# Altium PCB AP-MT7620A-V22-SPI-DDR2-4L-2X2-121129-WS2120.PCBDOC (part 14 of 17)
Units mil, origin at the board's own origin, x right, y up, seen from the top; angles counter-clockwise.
Board outline 7316 x 4279 mil, 4 copper layers (Top, Inner Layer 2, Inner Layer 3, Bottom), stack 35.4 mil thick; 640 components, 473 nets, 2041 pads, 2358 vias.
Unrouted connection lines stored in the file: 11.
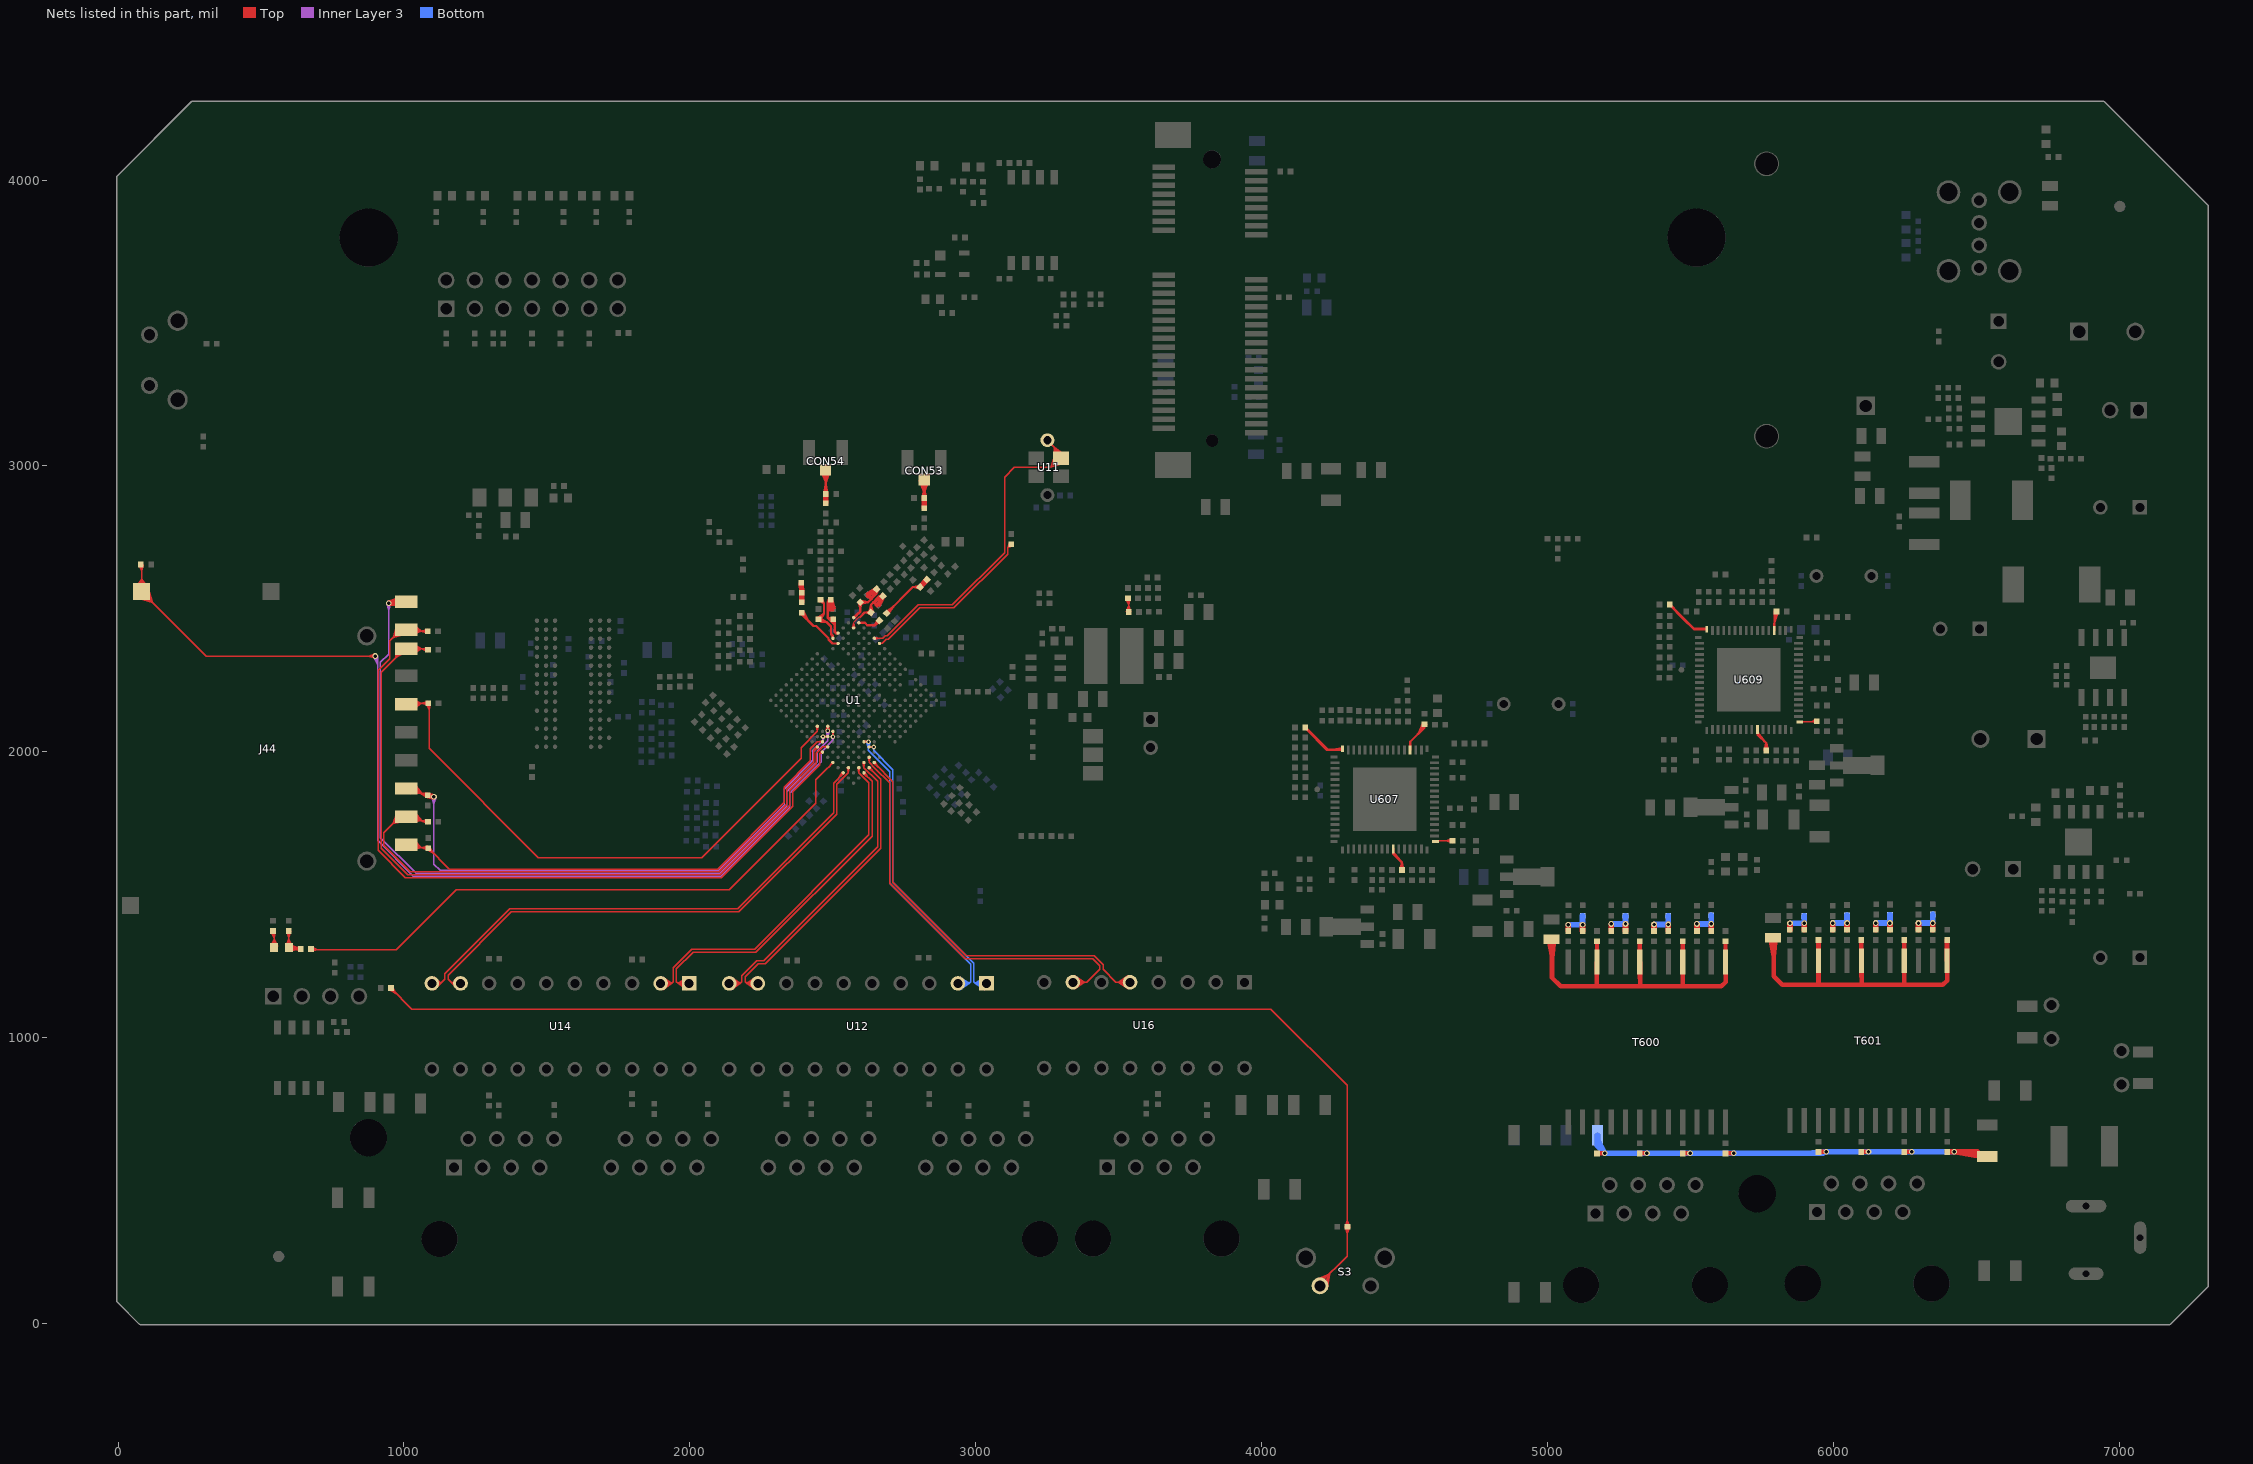
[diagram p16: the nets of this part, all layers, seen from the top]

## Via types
v1: diameter 20, hole 12, Top to Bottom, 2117 vias
v2: diameter 16, hole 8, Top to Bottom, 241 vias

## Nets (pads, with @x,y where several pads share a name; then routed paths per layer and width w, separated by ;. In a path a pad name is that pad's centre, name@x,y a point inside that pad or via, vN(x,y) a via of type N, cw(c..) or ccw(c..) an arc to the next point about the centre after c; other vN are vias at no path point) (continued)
PMCT_HV_GE_4-ETHERNET: C732.1 C735.1 R795.1 R796.1 R797.1 R798.1 R803.1 R804.1 R805.1 R806.1 | length 2327.8
  Top w15: R797.1@5473.05,595.01 R797.1@5474.04,596 ; R797.1@5473.05,595.01 v1(5499,596) ; R797.1@5473.05,595.01 v1(5499,596) ; R797.1@5474.04,596 v1(5499,596) ; R797.1@5474.04,596 v1(5499,596) ; R805.1@6248.05,600.01 R805.1@6249.04,601 ; R805.1@6248.05,600.01 v1(6274,601) ; R805.1@6248.05,600.01 v1(6274,601) ; R805.1@6249.04,601 v1(6274,601) ; R805.1@6249.04,601 v1(6274,601) ; R795.1@5173.05,595.01 5174.04,596 v1(5200,596) R795.1@5173.05,595.01 ; R796.1@5323.05,595.01 5324.04,596 v1(5348,596) R796.1@5323.05,595.01 ; R798.1@5623.05,595.01 5624.04,596 v1(5652,596) R798.1@5623.05,595.01 ; R803.1@5948.05,600.01 5949.04,601 v1(5975,601) R803.1@5948.05,600.01 ; R804.1@6098.05,600.01 6099.04,601 v1(6123,601) R804.1@6098.05,600.01
  Top w20: R806.1@6398.05,600.01 v1(6423,601) ; R806.1@6398.05,601.01 v1(6423,601) ; v1@6431.84,601 C732.1@6522.25,584.88 ; 6494.56,589.82 v1(6423,601) ; C732.1@6538,584.88 6538,588 6516,588 6503,601 v1(6423,601)
  Bottom w20: C735.1@5175.24,658.56 5175.06,658.38 5175.06,622 ; 5898.21,596.01 v1(5975,601) ; v1(6423,601) v1(6274,601) v1(6123,601) v1(5975,601) ; 5175.06,622 v1@5200,597.06 ; 5175.06,622 v1(5200,596) ; v1(5200,596) v1(5348,596) v1(5499,596) v1(5652,596) 5963.01,596.01 5968,601 v1(5975,601) ; v1(5200,596) v1@5200,597.06 ; v1(5200,596) 5175.24,642.81 v1@5200,597.06
POWERLED_6-LED1: D7.1 R158.1 | length 377.5
  Top w4.5: R158.1@534.68,1370.45 546.41,1348.56 ; D7.1@534.93,1320.51 546.41,1345.5 ; R158.1@538.85,1372.21 546.41,1348.56 ; D7.1@539.22,1318.96 546.41,1345.5 ; D7.1@543.66,1318.14 546.41,1345.5 ; R158.1@545.23,1373.37 546.41,1348.56 ; D7.1@546.41,1316 546.41,1369.59 542,1374 R158.1@542,1373 546.41,1348.56 ; D7.1@546.41,1318 546.41,1345.5 ; D7.1@549.16,1318.14 546.41,1345.5 ; R158.1@549.75,1373.17 546.41,1348.56 ; D7.1@553.6,1318.96 546.41,1345.5 ; D7.1@557.89,1320.51 546.41,1345.5
PRSET_IP1001-2_1-CPU-RT0: R744.1 U609.17 | length 154.1
  Top w5: U609.17@5882.16,2104.41 5895,2104.41 ; 5908.97,2105 U609.17@5889.05,2104.41 ; R744.1@5938.91,2113.89 5927,2104.41 ; R744.1@5941.43,2099.57 5927,2104.41 ; U609.17@5889.05,2104.41 5895.59,2105 ; U609.17@5889.05,2104.41 5895,2104.41 ; U609.17@5889.05,2104.41 5895,2104.41 ; U609.17@5889.05,2104.41 5895.59,2105 ; 5895,2104.41 5895.59,2105 ; 5895.59,2105 5926.41,2105 5927,2104.41 ; 5927,2104.41 5940.35,2104.41 5942.99,2107.05 R744.1@5941.99,2107.05 5927,2104.41
PRSET_IP1001_1-CPU-RT0: R723.1 U607.17 | length 159.8
  Top w5: U607.17@4608.16,1686.41 4608.16,1689.06 4668.98,1689.06 R723.1@4667.99,1689.05 4642.99,1689.06 ; U607.17@4615.05,1686.41 4635.16,1689.06 ; R723.1@4666.86,1681.64 4642.99,1689.06 ; R723.1@4666.87,1696.47 4642.99,1689.06
PTC1_GE_2_4-ETHERNET: C813.1 R801.1 R802.1 | length 275
  Top w20: R801.1@6298,1378.06 R801.1@6298.05,1378.01 v1(6298,1401) ; R801.1@6298,1378.06 v1(6298,1401) ; R801.1@6298,1378.06 v1(6298,1401) ; R802.1@6348.05,1378.01 v1(6348.05,1401) R802.1@6348.05,1378.01
  Bottom w20: v1(6348.05,1401) v1(6298,1401) v1(6348.05,1401) ; v1(6348.05,1401) C813.1@6348,1431 C813.1@6348,1431 v1(6348.05,1401)
PTC1_GE_4-ETHERNET: C809.1 R789.1 R790.1 | length 309.9
  Top w20: R789.1@5523,1373.06 R789.1@5523.05,1373.01 v1(5523,1398) ; R789.1@5523,1373.06 v1(5523,1398) ; R789.1@5523,1373.06 v1(5523,1398) ; R790.1@5573,1373.06 v1(5573,1398) ; R790.1@5573,1373.06 R790.1@5573.05,1373.01 v1(5573,1398) ; R790.1@5573,1373.06 v1(5573,1398)
  Bottom w20: v1(5573,1398) v1(5523,1398) v1(5573,1398) ; v1(5573,1398) C809.1@5573,1428 v1(5573,1398)
PTC2_GE_2_4-ETHERNET: C812.1 R799.1 R800.1 | length 295.9
  Top w20: R799.1@6148,1378.06 R799.1@6148.05,1378.01 v1(6148,1401) ; R799.1@6148,1378.06 v1(6148,1401) ; R799.1@6148,1378.06 v1(6148,1401) ; R800.1@6198,1378.06 v1(6198,1401) ; R800.1@6198,1378.06 R800.1@6198.05,1378.01 v1(6198,1401) ; R800.1@6198,1378.06 v1(6198,1401)
  Bottom w20: v1(6198,1401) v1(6148,1401) v1(6198,1401) ; v1(6198,1401) C812.1@6198,1430 v1(6198,1401)
PTC2_GE_4-ETHERNET: C808.1 R787.1 R788.1 | length 277
  Top w20: R788.1@5423,1373.06 v1(5423,1396) ; R788.1@5423,1373.06 R788.1@5423.05,1373.01 v1(5423,1396) ; R788.1@5423,1373.06 v1(5423,1396) ; R787.1@5373,1373.06 R787.1@5373.05,1373.01 v1(5373,1396) R787.1@5373,1373.06
  Bottom w20: v1(5423,1396) v1(5373,1396) v1(5423,1396) ; v1(5423,1396) C808.1@5423.05,1427 C808.1@5423.05,1427 v1(5423,1396)
PTC3_GE_2_4-ETHERNET: C815.1 R793.1 R794.1 | length 268.9
  Top w20: R793.1@5998,1378.06 R793.1@5998.05,1378.01 v1(5998,1401) ; R793.1@5998,1378.06 v1(5998,1401) ; R793.1@5998,1378.06 v1(5998,1401) ; v1(6048,1401) v1(6048,1401) R794.1@6048.05,1378.01 v1(6048,1401)
  Bottom w20: v1(6048,1401) v1(5998,1401) v1(6048,1401) ; v1(6048,1401) C815.1@6048,1428 v1(6048,1401)
PTC3_GE_4-ETHERNET: C807.1 R785.1 R786.1 | length 258
  Top w20: v1(5223,1398) v1(5223,1398) R785.1@5223.05,1373.01 v1(5223,1398) ; v1(5273,1398) v1(5273,1398) R786.1@5273.05,1373.01 v1(5273,1398)
  Bottom w20: v1(5273,1398) v1(5223,1398) v1(5273,1398) ; v1(5273,1398) C807.1@5273.05,1427 C807.1@5273.05,1427 v1(5273,1398)
PTC4_GE_2_4-ETHERNET: C811.1 R791.1 R792.1 | length 307.1
  Top w20: R791.1@5848.05,1378.01 R791.1@5848.5,1378.46 ; R791.1@5848.05,1378.01 v1(5848.5,1400.5) ; R791.1@5848.05,1378.01 v1(5848.5,1400.5) ; R791.1@5848.5,1378.46 v1(5848.5,1400.5) ; R791.1@5848.5,1378.46 v1(5848.5,1400.5) ; R792.1@5898,1378.06 R792.1@5898.05,1378.01 v1(5898,1400.5) ; R792.1@5898,1378.06 v1(5898,1400.5) ; R792.1@5898,1378.06 v1(5898,1400.5)
  Bottom w20: v1(5898,1400.5) v1(5848.5,1400.5) v1(5898,1400.5) ; v1(5898,1400.5) C811.1@5898,1426 v1(5898,1400.5)
PTC4_GE_4-ETHERNET: C806.1 R783.1 R784.1 | length 275.5
  Top w20: R784.1@5123,1373.06 v1(5123,1395.5) ; R784.1@5123,1373.06 R784.1@5123.05,1373.01 v1(5123,1395.5) ; R784.1@5123,1373.06 v1(5123,1395.5) ; v1(5073,1395.5) 5073.05,1395.45 R783.1@5073.05,1373.01 v1(5073,1395.5)
  Bottom w20: v1(5123,1395.5) v1(5073,1395.5) v1(5123,1395.5) ; v1(5123,1395.5) C806.1@5123.05,1427 C806.1@5123.05,1427 v1(5123,1395.5)
PTCT_GE_2_4-ETHERNET: C726.2 C727.2 C728.2 C730.2 L622.2 T601.1 T601.4 T601.7 T601.10 | length 1972.8
  Top w15: T601.7@6098.05,1269.54 C727.2@6098.05,1342.01 T601.7@6098.05,1303.79 ; T601.4@6248.05,1269.54 C728.2@6248.05,1342.01 T601.4@6248.05,1303.79
  Top w16: L622.2@5780.09,1348.66 5791.05,1284.46 ; L622.2@5798.04,1349.22 5791.05,1284.46 ; T601.10@5948.05,1235.29 5948.05,1185.01 ; T601.10@5948.05,1269.54 5948.05,1185.01 ; T601.7@6098.05,1235.29 6099.05,1185.01 ; T601.7@6098.05,1269.54 6099.05,1268.54 6099.05,1185.01 ; T601.4@6248.05,1235.29 6248.05,1185.01 ; T601.4@6248.05,1269.54 6248.05,1185.01 ; T601.1@6398.05,1235.29 6398.05,1200.01 ; T601.1@6398.05,1269.54 6398.05,1200.01 ; 5791.05,1284.46 L622.2@5789.05,1349.56 5791.05,1347.56 5791.05,1215.01 5821.05,1185.01 5948.05,1185.01 ; 5948.05,1185.01 6099.05,1185.01 ; 6099.05,1185.01 6248.05,1185.01 ; 6248.05,1185.01 6383.05,1185.01 6398.05,1200.01
  Top w18: T601.10@5948.05,1269.54 C726.2@5948.05,1342.01 T601.10@5948.05,1303.79 ; T601.1@6398,1278 C730.2@6398,1342 ; T601.1@6398.05,1269.54 6398,1269.59 C730.2@6398,1342 ; T601.1@6398.05,1303.79 C730.2@6398,1342
PTCT_GE_4-ETHERNET: C714.2 C715.2 C716.2 C717.2 L616.2 T600.1 T600.4 T600.7 T600.10 | length 1908.8
  Top w15: T600.10@5173.05,1264.54 C714.2@5173.05,1337.01 T600.10@5173.05,1298.79 ; T600.7@5323.05,1264.54 C715.2@5323.05,1337.01 T600.7@5323.05,1298.79 ; T600.4@5473.05,1264.54 C716.2@5473.05,1337.01 T600.4@5473.05,1298.79 ; T600.1@5623.05,1264.54 C717.2@5623.05,1337.01 T600.1@5623.05,1298.79
  Top w16: L616.2@5005.09,1343.66 5016.05,1279.46 ; L616.2@5023.04,1344.22 5016.05,1279.46 ; T600.10@5173.05,1230.29 5173.05,1180.01 ; T600.10@5173.05,1264.54 5173.05,1180.01 ; T600.7@5323.05,1230.29 5324.05,1180.01 ; T600.7@5323.05,1264.54 5324.05,1263.54 5324.05,1180.01 ; T600.4@5473.05,1230.29 5473.05,1180.01 ; T600.4@5473.05,1264.54 5473.05,1180.01 ; T600.1@5623.05,1230.29 5623.05,1195.01 ; T600.1@5623.05,1264.54 5623.05,1195.01 ; 5016.05,1279.46 L616.2@5014.05,1344.56 5016.05,1342.56 5016.05,1210.01 5046.05,1180.01 5173.05,1180.01 ; 5173.05,1180.01 5324.05,1180.01 ; 5324.05,1180.01 5473.05,1180.01 ; 5473.05,1180.01 5608.05,1180.01 5623.05,1195.01
PWR_LED: R372.1 U1.U13 | length 2293.8
  Top w4.5: R372.1@674.95,1306.75 698.7,1308 ; R372.1@675.49,1313.21 698.7,1308 ; R372.1@675.62,1302.27 698.7,1308 ; R372.1@676.9,1317.51 698.7,1308 ; U1.U13@2497.72,1965.08 2490.76,1953 ; U1.U13@2500.62,1962.86 2490.76,1953 ; U1.U13@2502.84,1959.96 2490.76,1953 ; 698.7,1308 R372.1@675,1310 676,1309 676,1308 974,1308 1184,1518 2138,1518 2440,1820 2440,1902.24 2475,1937.24 2475.8,1937.24 2490.76,1952.2 2490.76,1953
PWRLED_6-LED1: D7.2 R159.2 R372.2 | length 2261.9
  Top w4.5: D7.2@586.11,1320.51 597.59,1345.5 ; R159.2@589.39,1371.53 597.59,1349.49 ; D7.2@590.4,1318.96 597.59,1345.5 ; R159.2@593.76,1372.69 597.59,1349.49 ; D7.2@594.84,1318.14 597.59,1345.5 ; D7.2@597.12,1306.76 626.47,1308.49 ; D7.2@597.2,1311.28 626.47,1308.49 ; D7.2@597.48,1311.25 625.92,1311.44 ; D7.2@597.6,1313.25 625.18,1314.76 ; D7.2@597.59,1318 597.59,1345.5 ; D7.2@597.65,1311.25 625.49,1313.21 ; D7.2@597.65,1318.75 625.15,1316.76 ; D7.2@597.74,1302.25 626.47,1308.49 ; D7.2@597.73,1313.25 625.09,1316 ; D7.2@597.73,1318.75 625.09,1316 ; D7.2@597.8,1316.74 625.49,1313.21 ; D7.2@597.86,1306.75 625.92,1311.44 ; D7.2@597.85,1318.74 625.18,1314.76 ; D7.2@597.97,1316.72 625.92,1311.44 ; D7.2@598.22,1308.78 625.18,1314.76 ; D7.2@598.23,1316.67 626.47,1308.49 ; D7.2@598.33,1306.79 625.49,1313.21 ; D7.2@598.35,1323.21 625.15,1316.76 ; D7.2@598.55,1308.81 625.09,1316 ; D7.2@598.55,1323.19 625.09,1316 ; D7.2@598.74,1308.84 625.15,1316.76 ; D7.2@598.74,1321.16 625.49,1313.21 ; D7.2@598.86,1323.14 625.18,1314.76 ; D7.2@598.97,1302.33 625.92,1311.44 ; D7.2@599.16,1321.08 625.92,1311.44 ; D7.2@599.57,1304.42 625.18,1314.76 ; D7.2@599.74,1302.45 625.49,1313.21 ; D7.2@599.82,1320.9 626.47,1308.49 ; D7.2@599.78,1327.54 625.15,1316.76 ; D7.2@600.1,1304.52 625.09,1316 ; D7.2@600.1,1327.48 625.09,1316 ; R159.2@600.25,1372.86 597.59,1349.49 ; D7.2@600.34,1318.14 597.59,1345.5 ; D7.2@600.41,1304.59 625.15,1316.76 ; D7.2@600.39,1325.41 625.49,1313.21 ; D7.2@600.6,1327.36 625.18,1314.76 ; D7.2@601.04,1325.23 625.92,1311.44 ; D7.2@602.05,1324.87 626.47,1308.49 ; R159.2@604.67,1371.92 597.59,1349.49 ; D7.2@604.78,1318.96 597.59,1345.5 ; D7.2@609.07,1320.51 597.59,1345.5 ; R372.2@636.1,1302.81 613.74,1316 ; R372.2@638.05,1306.89 613.74,1316 ; R372.2@639.55,1313.2 613.74,1316 ; R372.2@639.65,1317.72 613.74,1316 ; D7.2@597.59,1314 625.49,1313.21 ; D7.2@597.59,1314 626.47,1308.49 ; D7.2@597.59,1314 625.92,1311.44 ; D7.2@597.59,1316 597.59,1373.41 597,1374 R159.2@597,1373 597.59,1349.49 ; D7.2@597.59,1316 634,1316 640,1310 R372.2@639,1310 613.74,1316 ; D7.2@597.59,1316 625.15,1316.76 ; D7.2@597.59,1316 613.74,1316 ; D7.2@597.59,1316 625.18,1314.76 ; D7.2@597.59,1316 613.74,1316 ; D7.2@597.59,1316 613.74,1316 ; D7.2@597.59,1316 613.74,1316 ; D7.2@597.59,1316 613.74,1316 ; D7.2@597.8,1313.26 625.15,1316.76 ; D7.2@597.82,1313.26 613.74,1316 ; D7.2@597.82,1313.26 613.74,1316 ; D7.2@597.82,1313.26 613.74,1316 ; D7.2@597.82,1313.26 613.74,1316 ; D7.2@597.82,1313.26 613.74,1316 ; D7.2@597.82,1318.74 613.74,1316 ; D7.2@597.82,1318.74 613.74,1316 ; D7.2@597.82,1318.74 613.74,1316 ; D7.2@597.82,1318.74 613.74,1316 ; D7.2@597.82,1318.74 613.74,1316 ; D7.2@599.22,1308.93 613.74,1316 ; D7.2@599.22,1308.93 613.74,1316 ; D7.2@599.22,1308.93 613.74,1316 ; D7.2@599.22,1308.93 613.74,1316 ; D7.2@599.22,1308.93 613.74,1316 ; D7.2@599.22,1323.07 613.74,1316 ; D7.2@599.22,1323.07 613.74,1316 ; D7.2@599.22,1323.07 613.74,1316 ; D7.2@599.22,1323.07 613.74,1316 ; D7.2@599.22,1323.07 613.74,1316 ; D7.2@601.87,1305.06 613.74,1316 ; D7.2@601.87,1305.06 613.74,1316 ; D7.2@601.87,1305.06 613.74,1316 ; D7.2@601.87,1305.06 613.74,1316 ; D7.2@601.87,1305.06 613.74,1316 ; D7.2@601.87,1326.94 613.74,1316 ; D7.2@601.87,1326.94 613.74,1316 ; D7.2@601.87,1326.94 613.74,1316 ; D7.2@601.87,1326.94 613.74,1316 ; D7.2@601.87,1326.94 613.74,1316
REFCLK_OUT_IP1001-2_1-CPU-RT0: C663.1 U609.10 | length 192.7
  Top w8: U609.10@5734.52,2078.82 5734.52,2061.05 ; C663.1@5759.03,2005.76 5764.99,2030.58 ; 5759.36,2036.21 U609.10@5734.52,2067.99 ; C663.1@5764.99,2004.05 C663.1@5764.99,2005.05 5764.99,2030.58 ; C663.1@5770.95,2005.76 5764.99,2030.58 ; 5734.52,2061.05 5764.99,2030.58 ; 5734.52,2061.05 U609.10@5734.52,2067.99 ; 5734.52,2061.05 U609.10@5734.52,2067.99
REFCLK_OUT_IP1001_1-CPU-RT0: C656.1 U607.10 | length 192.7
  Top w8: U607.10@4460.52,1660.82 4460.52,1643.05 ; C656.1@4485.03,1587.76 4490.99,1612.58 ; 4485.36,1618.21 U607.10@4460.52,1649.99 ; C656.1@4490.99,1586.05 C656.1@4490.99,1587.05 4490.99,1612.58 ; C656.1@4496.95,1587.76 4490.99,1612.58 ; 4460.52,1643.05 4490.99,1612.58 ; 4460.52,1643.05 U607.10@4460.52,1649.99 ; 4460.52,1643.05 U607.10@4460.52,1649.99
RF0_PA2_1-CPU-RT0: L627.1 U1.A2 | length 128.4
  Top w8: U1.A2@2591.1,2451.43 2612.57,2451.43 2621,2443 2647,2443 ; L627.1@2658.51,2462.93 2647,2443 ; L627.1@2663.27,2459.27 2647,2443 ; L627.1@2666.93,2454.51 2647,2443
RF0_PA2_1_1-CPU-RT0: C82.1 L5.1 L627.2 | length 709.7
  Top w8: L627.2@2684.88,2489.33 2712.77,2508.77 L627.2@2693.33,2480.88 ; L627.2@2688.73,2484.73 2780.27,2576.27 ; C82.1@2800.96,2579.91 L5.1@2824.09,2605.28 ; C82.1@2801.65,2580.67 L5.1@2828.61,2601.61 ; C82.1@2802.46,2581.3 L5.1@2832.69,2597.37 ; C82.1@2805.02,2570.31 2780.27,2576.27 ; C82.1@2805.02,2582.23 2780.27,2576.27 ; C82.1@2809.83,2571.89 L5.1@2832.69,2597.37 ; C82.1@2810.52,2572.66 L5.1@2828.61,2601.61 ; C82.1@2811.06,2573.52 L5.1@2824.09,2605.28 ; L5.1@2824.66,2606.12 C82.1@2805.73,2578.73 ; L5.1@2829.27,2602.27 C82.1@2805.73,2578.73 ; L5.1@2833.12,2597.66 C82.1@2805.73,2578.73 ; 2780.27,2576.27 C82.1@2805.73,2576.27 ; 2780.27,2576.27 C82.1@2805.73,2576.27 ; C82.1@2805.73,2576.27 C82.1@2805.73,2578.73 ; C82.1@2805.73,2576.27 L5.1@2828.61,2601.61 ; C82.1@2805.73,2576.27 L5.1@2832.69,2597.37 ; C82.1@2805.73,2576.27 L5.1@2824.09,2605.28
RF0_PA_OUTN_1-CPU-RT0: C842.1 L624.1 U1.B2 | length 754.8
  Top w4: U1.B2@2569.12,2433.75 2573,2451.5 ; U1.B2@2576.88,2433.75 2573,2451.5 ; 2596,2472 2593.57,2472 2576,2454.43 2575.93,2454.43 2573,2451.5 ; 2573,2451.5 U1.B2@2573,2433.33 2573,2451.5
  Top w8: 2596,2472 2611.27,2487.27 2615.85,2487.27 ; C842.1@2628.02,2488.06 2633.83,2514.72 ; C842.1@2632.95,2493.34 2615.85,2487.27 ; C842.1@2633.05,2481.51 2615.85,2487.27 ; C842.1@2639.95,2488.13 2633.83,2514.72 ; 2654.73,2517.09 L624.1@2678.48,2539.4 ; 2655.53,2508.39 2641.92,2522.81 ; 2661.33,2518.73 2641.92,2522.81 ; 2664.37,2510.03 L624.1@2678.48,2539.4 ; L624.1@2671.96,2549.44 2641.92,2522.81 ; L624.1@2673.54,2544.67 L624.1@2675.59,2544.67 ; 2615.85,2487.27 C842.1@2633.99,2487.44 ; 2615.85,2487.27 C842.1@2633.99,2487.44 ; 2633.83,2505.58 2633.83,2514.72 ; 2633.83,2505.58 C842.1@2633.99,2487.44 ; 2633.83,2505.58 2628.07,2488.37 2633.83,2505.58 ; 2633.83,2505.58 2639.9,2488.48 2633.83,2505.58 ; 2633.83,2505.58 C842.1@2633.99,2487.44 ; 2633.83,2505.58 C842.1@2633.99,2487.44 ; 2633.83,2514.72 2663.77,2544.67 L624.1@2675.59,2544.67 ; 2633.83,2514.72 C842.1@2633.99,2487.44 ; 2641.92,2522.81 L624.1@2678.48,2539.4 ; 2641.92,2522.81 L624.1@2675.59,2544.67 ; 2641.92,2522.81 2659.22,2513.12 L624.1@2678.48,2539.4
RF0_PA_OUTP_1-CPU-RT0: C841.1 L623.1 U1.A1 | length 792
  Top w8: C841.1@2590.31,2522.47 2595.99,2505.24 ; 2595.3,2489.69 U1.A1@2573,2469.52 2574.07,2468.45 2595.99,2490.37 2595.99,2505.24 ; C841.1@2596.84,2517.41 2623.76,2523.13 ; C841.1@2596.95,2529.34 2623.76,2523.13 ; C841.1@2602.14,2522.3 2595.99,2505.24 ; 2618.27,2543.82 2634.86,2534.23 ; 2618.41,2553.26 L623.1@2647.76,2571.79 ; 2626.44,2544.4 L623.1@2647.76,2571.79 ; 2627.08,2551.74 2634.86,2534.23 ; L623.1@2658.36,2566.24 2634.86,2534.23 ; 2595.99,2505.24 C841.1@2596.24,2523.38 ; 2595.99,2505.24 C841.1@2596.24,2523.38 ; C841.1@2596.24,2523.38 2614.38,2523.13 ; C841.1@2596.24,2523.38 2614.38,2523.13 ; C841.1@2596.24,2523.38 2623.76,2523.13 ; C841.1@2596.24,2523.38 2614.38,2523.13 ; 2614.38,2523.13 2623.76,2523.13 ; 2614.38,2523.13 2597.31,2529.28 2614.38,2523.13 ; 2614.38,2523.13 2597.15,2517.45 2614.38,2523.13 ; 2623.76,2523.13 2653.27,2552.64 ; 2634.86,2534.23 L623.1@2647.76,2571.79 ; 2634.86,2534.23 L623.1@2653.27,2569.41 ; 2634.86,2534.23 2622.04,2548.48 L623.1@2647.76,2571.79 ; 2653.27,2552.64 L623.1@2653.27,2569.41 ; 2653.27,2552.64 2659.18,2568.34 2653.27,2552.64 ; 2653.27,2552.64 2647.37,2568.34 2653.27,2552.64 ; 2653.27,2552.64 L623.1@2653.27,2569.41
RF1_PA2_1-CPU-RT0: L628.1 U1.E2 | length 311.6
  Top w8: L628.1@2387.62,2482.9 2415.83,2457.17 ; L628.1@2396.97,2490.36 2415.83,2457.17 ; 2415.83,2457.17 L628.1@2392,2487 2393,2486 2393,2480 2433,2440 2442.1,2440 2485,2397.1 2485,2393 2498.95,2379.05 ; 2498.95,2379.05 U1.E2@2518.71,2379.05 2498.95,2379.05
RF1_PA2_1_1-CPU-RT0: C107.1 L12.1 L628.2 | length 876.8
  Top w8: L12.1@2384.06,2590.12 C107.1@2392,2556.89 ; C107.1@2386.02,2555.45 L628.2@2392,2523 ; C107.1@2386,2556.19 L12.1@2390.06,2589.96 ; C107.1@2386.06,2555.16 L12.1@2384.24,2589.38 ; C107.1@2386.12,2557.21 L12.1@2395.88,2589.84 ; C107.1@2386.22,2554.38 L628.2@2397.98,2523.55 ; L12.1@2396,2590.82 C107.1@2392,2556.89 ; C107.1@2397.7,2557.86 L12.1@2384.24,2589.38 ; C107.1@2397.78,2554.38 L628.2@2386.02,2523.55 ; C107.1@2397.94,2556.87 L12.1@2390.06,2589.96 ; C107.1@2397.98,2555.45 L628.2@2392,2523 ; C107.1@2398,2555.84 L12.1@2395.88,2589.84 ; L12.1@2384.24,2589.38 C107.1@2392,2556 ; L628.2@2386.02,2523.55 C107.1@2392,2556 ; L628.2@2386.02,2523.55 2386.02,2556.55 L12.1@2392,2590 ; L628.2@2386.02,2523.55 C107.1@2392,2556 ; L12.1@2390.06,2589.96 C107.1@2392,2556 ; L628.2@2392,2523 C107.1@2392,2556 ; L628.2@2392,2523 C107.1@2392,2556 ; C107.1@2392,2556 L12.1@2392,2590 ; C107.1@2392,2556 L628.2@2397.98,2523.55 ; C107.1@2392,2556 L12.1@2395.88,2589.84 ; C107.1@2392,2556.89 L12.1@2390,2591 L12.1@2392,2590 ; L12.1@2392,2590 2397.98,2556.53 L628.2@2397.98,2523.55
RF1_PA_OUTN_1-CPU-RT0: C844.1 L626.1 U1.E1 | length 405.9
  Top w8: C844.1@2446.24,2468.67 2469.76,2483.76 ; C844.1@2448.56,2458.17 2478,2454 ; C844.1@2452.58,2469.42 2478,2454 ; L626.1@2453.49,2527.13 2469.76,2519.1 ; C844.1@2454.67,2460.24 2469.76,2483.76 ; L626.1@2461.9,2535.46 2469.76,2519.1 ; C844.1@2450,2464 2460,2454 2478,2454 ; C844.1@2450,2464 2469.76,2483.76 ; C844.1@2450,2464 2478,2454 ; 2469.76,2483.76 2469.76,2519.1 ; 2469.76,2519.1 2456.93,2531.93 2456.93,2532 L626.1@2457,2532 2469.76,2519.1 ; 2478,2454 2494,2438 2494,2413.03 ; 2494,2413.03 2500.62,2406.41 ; 2494,2413.03 U1.E1@2500.62,2397.14 ; U1.E1@2500.62,2397.14 2500.62,2406.41 ; U1.E1@2500.62,2397.14 2500.62,2406.41
RF1_PA_OUTP_1-CPU-RT0: C843.1 L625.1 U1.D1 | length 624.3
  Top w8: L625.1@2487.11,2533.14 2482.76,2494.79 ; 2496,2499.93 L625.1@2498.64,2529.96 ; C843.1@2496.44,2461.74 2507,2443.76 ; 2499.58,2505.49 2482.76,2494.79 ; C843.1@2499.9,2458.38 2482.76,2468 ; C843.1@2502.31,2469.99 2482.76,2468 ; 2502.68,2494.04 2482.76,2494.79 ; 2507.87,2501.26 L625.1@2498.64,2529.96 ; C843.1@2507.97,2464.59 2507,2443.76 ; 2482.76,2468 2482.76,2521.76 ; 2482.76,2468 C843.1@2494.76,2456 ; 2482.76,2468 C843.1@2502,2464 ; 2482.76,2494.79 L625.1@2498.64,2529.96 ; 2482.76,2494.79 L625.1@2493,2532 ; 2482.76,2494.79 2502,2500 L625.1@2498.64,2529.96 ; 2482.76,2521.76 L625.1@2493,2532 ; 2482.76,2521.76 2496.27,2526.97 2482.76,2521.76 ; 2482.76,2521.76 2487.97,2535.27 2482.76,2521.76 ; 2482.76,2521.76 L625.1@2493,2532 ; C843.1@2494.76,2456 2507,2443.76 ; C843.1@2494.76,2456 2502.38,2463.62 2502.38,2464 C843.1@2502,2464 ; C843.1@2502,2464 2507,2443.76 ; 2507,2419 2510.76,2415.24 U1.D1@2518.71,2415.24 2507,2419 ; 2507,2419 2507,2443.76
RF_XI_1-CPU-RT0: U1.A5 U11.3 U33.2 | length 2006.7
  Top w5: U1.A5@2645.38,2397.14 2674.69,2397.14 2683.55,2406 2691.05,2406 2799.05,2514 2918,2514 3101,2697 3101,2960.64 3135.54,2995.19 3263.06,2995.19 ; U1.A5@2645.63,2393.75 2668.73,2397.14 U1.A5@2645.63,2400.54 ; U33.2@3251,3090.06 3275,3066.06 ; U11.3@3273.73,3022.03 3275,3066.06 ; U11.3@3276.3,3037.44 3263.06,2995.19 ; U11.3@3278.84,3022.18 3275,3066.06 ; U11.3@3281.09,3035.63 3263.06,2995.19 ; U11.3@3283.84,3022.91 3275,3066.06 ; U11.3@3285.58,3033.31 3263.06,2995.19 ; U11.3@3288.7,3024.19 3275,3066.06 ; U11.3@3289.75,3030.52 3263.06,2995.19 ; U11.3@3298.39,3021.88 3263.06,2995.19 ; U11.3@3299.67,3029.56 3275,3066.06 ; U11.3@3301.18,3017.71 3263.06,2995.19 ; U11.3@3303.5,3013.21 3263.06,2995.19 ; U11.3@3303.66,3032.61 3275,3066.06 ; U11.3@3305.31,3008.43 3263.06,2995.19 ; U11.3@3307.31,3036.11 3275,3066.06 ; U11.3@3310.56,3040.06 3275,3066.06 ; 3263.06,2995.19 U11.3@3294.37,3026.5 ; 3263.06,2995.19 U11.3@3294.37,3026.5 ; 3275,3066.06 3275,3035 3289.75,3020.25 3295,3025.5 3297.31,3025.5 U11.3@3298.31,3026.5 U11.3@3294.37,3026.5 ; 3275,3066.06 U11.3@3294.37,3026.5
RF_XO_1-CPU-RT0: R108.1 U1.A6 | length 678.1
  Top w5: U1.A6@2664.12,2375.7 2672.5,2379.05 ; U1.A6@2664.12,2382.39 2672.5,2379.05 ; R108.1@3117.66,2730 3112,2714 ; R108.1@3124,2726 3112,2714 ; R108.1@3128,2719.66 3112,2714 ; 2672.5,2379.05 U1.A6@2663.48,2379.05 2672.5,2379.05 ; 2672.5,2379.05 2687.46,2394 2693.63,2394 2803.63,2504 2924,2504 3112,2692 3112,2714
RFOUT_G0: C88.1 CON53.1 L7.2 | length 762.3
  Top w8: CON53.1@2804.57,2949.16 2820,2908.29 ; CON53.1@2812.34,2951.3 2820,2908.29 ; L7.2@2814.02,2852.53 2820,2886 L7.2@2825.98,2852.53 ; C88.1@2814.02,2887.47 L7.2@2820,2854 ; C88.1@2814.02,2888.47 L7.2@2814.34,2854.33 ; C88.1@2814.02,2888.53 2820,2922 C88.1@2825.98,2888.53 ; C88.1@2814.19,2886.49 L7.2@2825.66,2854.33 ; L7.2@2820,2852 C88.1@2820,2888 ; CON53.1@2820,2951.98 2820,2908.29 ; CON53.1@2820,2952.96 C88.1@2820,2888 ; C88.1@2825.81,2886.49 L7.2@2814.34,2854.33 ; C88.1@2825.98,2887.47 L7.2@2820,2854 ; C88.1@2825.98,2888.47 L7.2@2825.66,2854.33 ; CON53.1@2827.66,2951.3 2820,2908.29 ; CON53.1@2835.43,2949.16 2820,2908.29 ; L7.2@2814.34,2854.33 C88.1@2820,2888 ; L7.2@2820,2854 C88.1@2820,2888 ; C88.1@2820,2888 L7.2@2825.66,2854.33
RFOUT_G1: C100.1 CON54.1 L10.2 | length 723.9
  Top w8: CON54.1@2459.64,2982.81 2476,2942.28 ; CON54.1@2467.36,2985.13 2476,2942.28 ; C100.1@2470.02,2902.53 2476,2936 C100.1@2481.98,2902.53 ; C100.1@2470.03,2901.44 L10.2@2476,2870 ; C100.1@2470.03,2902.56 L10.2@2470.03,2870.56 ; C100.1@2470.24,2900.33 L10.2@2481.97,2870.56 ; CON54.1@2475,2985.98 2476,2942.28 ; CON54.1@2475,2986.96 2476,2985.96 C100.1@2476,2902 ; C100.1@2481.76,2900.33 L10.2@2470.03,2870.56 ; C100.1@2481.97,2901.44 L10.2@2476,2870 ; C100.1@2481.97,2902.56 L10.2@2481.97,2870.56 ; CON54.1@2482.67,2985.48 2476,2942.28 ; CON54.1@2490.49,2983.52 2476,2942.28 ; L10.2@2470.03,2870.56 C100.1@2476,2902 ; L10.2@2470.03,2870.56 C100.1@2476,2902 ; L10.2@2476,2870 C100.1@2476,2902 ; L10.2@2476,2870 C100.1@2476,2902 ; C100.1@2476,2902 L10.2@2481.97,2870.56
RGMII_SEL_IP1001-2_1-CPU-RT0: R743.1 U609.36 | length 215.9
  Top w8: U609.36@5793.57,2425.28 5793.99,2425.7 5793.99,2482.99 5802,2491 R743.1@5801,2491 5793.99,2452.73 ; U609.36@5793.57,2436.11 5793.99,2465.03 ; R743.1@5795.03,2491.62 5793.99,2452.73 ; R743.1@5806.8,2489.47 5793.99,2452.73
RGMII_SEL_IP1001_1-CPU-RT0: R718.1 U607.36 | length 319.1
  Top w8: U607.36@4519.57,2007.28 4519.99,2007.7 4519.99,2035 ; U607.36@4519.57,2018.11 4519.99,2035 ; R718.1@4564.72,2099.84 4548.69,2063.7 ; R718.1@4570,2098 R718.1@4570,2097 ; R718.1@4574.79,2093.39 4548.69,2063.7 ; 4519.99,2035 4570,2085.01 ; 4548.69,2063.7 R718.1@4570,2097 ; 4570,2085.01 R718.1@4570,2097 ; 4570,2085.01 4575.81,2095.5 4570,2085.01 ; 4570,2085.01 4564.19,2095.5 4570,2085.01 ; 4570,2085.01 R718.1@4570,2097 ; 4570,2085.01 R718.1@4570,2097
RST_PBC: R355.2 R809.1 S3.1 | length 5144.8
  Top w4.5: R809.1@950.19,1167.93 973.99,1154.01 ; R809.1@952.78,1171.63 973.99,1154.01 ; R809.1@957.48,1176.1 973.99,1154.01 ; R809.1@961.31,1178.5 973.99,1154.01 ; S3.1@4187.96,153.76 4237.99,174.49 ; S3.1@4189.91,149.56 4237.99,174.49 ; S3.1@4192.19,145.59 4237.99,174.49 ; S3.1@4194.78,141.85 4237.99,174.49 ; S3.1@4197.66,138.35 4237.99,174.49 ; S3.1@4204.42,132 4204.42,140.92 4300,236.5 R355.2@4300,338.5 ; S3.1@4212.16,126.89 4237.99,174.49 ; S3.1@4216.23,124.9 4237.99,174.49 ; S3.1@4220.47,123.25 4237.99,174.49 ; S3.1@4224.86,121.95 4237.99,174.49 ; S3.1@4229.39,121.03 4237.99,174.49 ; R355.2@4293.31,337.55 4300,314.96 ; R355.2@4293.31,339.45 4300,362.05 ; R355.2@4297.75,338.41 4300,314.96 ; R355.2@4297.75,338.59 4300,362.05 ; R355.2@4304.23,338.14 4300,314.96 ; R355.2@4304.23,338.86 4300,362.05 ; R355.2@4308.58,336.9 4300,314.96 ; R355.2@4308.58,340.1 4300,362.05 ; 973.99,1154.01 R809.1@955,1174 954,1174 1028,1100 4033,1100 4300,833 R355.2@4300,338.5 ; 4300,314.96 R355.2@4301,338.5 ; R355.2@4300,338.5 R355.2@4301,338.5 ; 4300,362.05 R355.2@4301,338.5
RXDELAY_IP1001-2_1-CPU-RT0: R720.2 U609.48 | length 246
  Top w10: 5458.61,2483.43 R720.2@5427.99,2515.05 5426.99,2515.05 5477.04,2465 5477.04,2464.68 5512.5,2429.22 U609.48@5557.35,2429.22 5522.43,2429.22
RXDELAY_IP1001_1-CPU-RT0: R690.2 U607.48 | length 244.9
  Top w10: 4183.81,2053.47 R690.2@4153,2085 4152,2085 4154.72,2082.28 4155,2082.28 4230,2007.28 U607.48@4283.35,2007.28 ; 4247.27,2007.28 U607.48@4283.35,2011.22
RXIM0: U1.T15 U14.9 | length 2181.4
  Top w5: U14.9@1188.84,1168.8 1168.9,1190 ; U14.9@1188.84,1211.2 1168.9,1190 ; U14.9@1192.38,1172.81 1168.9,1190 ; U14.9@1192.38,1207.19 1168.9,1190 ; U14.9@1195.06,1177.24 1168.9,1190 ; U14.9@1195.06,1202.76 1168.9,1190 ; U14.9@1196.88,1181.99 1168.9,1190 ; U14.9@1196.88,1198.01 1168.9,1190 ; U14.9@1197.84,1186.91 1168.9,1190 ; U14.9@1197.84,1193.09 1168.9,1190 ; U14.9@1198,1190 1168.9,1190 ; U1.T15@2551.51,1944.44 2554.9,1926.7 ; U1.T15@2558.3,1944.44 2554.9,1926.7 ; 1168.9,1190 1154.46,1204.43 1154.46,1218.8 1375.67,1440 2171.56,1440 2514,1782.44 2514,1885.8 2554.9,1926.7 ; 2554.9,1926.7 U1.T15@2554.9,1944.76 2554.9,1926.7
RXIM1: U1.R17 U14.1 | length 1654.9
  Top w5: U14.1@1991.16,1167.94 1959,1190 ; U14.1@1991.16,1212.06 1959,1190 ; U14.1@1993.8,1172.4 1959,1190 ; U14.1@1993.8,1207.6 1959,1190 ; U14.1@1995.8,1177.1 1959,1190 ; U14.1@1995.8,1202.9 1959,1190 ; U14.1@1997.16,1181.95 1959,1190 ; U14.1@1997.16,1198.05 1959,1190 ; U14.1@1997.88,1186.91 1959,1190 ; U14.1@1997.88,1193.09 1959,1190 ; U14.1@1998,1190 1959,1190 ; U1.R17@2606.83,1924.21 2623.14,1910.86 ; U1.R17@2611.92,1928.71 2623.14,1910.86 ; 1959,1190 1953.5,1195.5 1953.5,1241 2011.5,1299 2231.06,1299 2637.5,1705.44 2637.5,1896.5 2609.19,1924.81 U1.R17@2609.19,1926.67 2623.14,1910.86
RXIM2: U1.P17 U12.9 | length 1455.4
  Top w5: U12.9@2231.16,1167.94 2199,1190 ; U12.9@2231.16,1212.06 2199,1190 ; U12.9@2233.8,1172.4 2199,1190 ; U12.9@2233.8,1207.6 2199,1190 ; U12.9@2235.8,1177.1 2199,1190 ; U12.9@2235.8,1202.9 2199,1190 ; U12.9@2237.16,1181.95 2199,1190 ; U12.9@2237.16,1198.05 2199,1190 ; U12.9@2237.88,1186.91 2199,1190 ; U12.9@2237.88,1193.09 2199,1190 ; U12.9@2238,1190 2199,1190 ; U1.P17@2625.08,1942.17 2642.07,1929.98 U1.P17@2629.88,1946.97 ; U1.P17@2627.29,1944.76 2668,1904.05 2668,1663.27 2263.56,1258.82 2239.38,1258.82 2193.5,1212.94 2193.5,1195.5 2199,1190
RXIM3: U1.M14 U12.2 | length 1537.8
  Top w8: U1.M14@2609.19,2035.24 2624.86,2035.24 U1.M14@2609.19,2035.24 ; U1.M14@2609.19,2035.24 v2(2625.1,2035) U1.M14@2609.19,2035.24
  Top w10: v2@2624.86,2035.24 v2(2625.1,2035)
  Bottom w5: v2@2619.63,2034.4 2625.1,2010 v2@2630.57,2034.4 ; v2(2625.1,2035) 2625.1,2004.9 2699,1931 2699,1540.11 2982.5,1256.61 2982.5,1195.5 2977,1190 ; U12.2@2938,1190 2977,1190 ; U12.2@2938.12,1186.91 2977,1190 ; U12.2@2938.12,1193.09 2977,1190 ; U12.2@2938.84,1181.95 2977,1190 ; U12.2@2938.84,1198.05 2977,1190 ; U12.2@2940.2,1177.1 2977,1190 ; U12.2@2940.2,1202.9 2977,1190 ; U12.2@2942.2,1172.4 2977,1190 ; U12.2@2942.2,1207.6 2977,1190 ; U12.2@2944.84,1167.94 2977,1190 ; U12.2@2944.84,1212.06 2977,1190
RXIM4: U1.N17 U16.5 | length 1901.3
  Top w5: U1.N17@2642.99,1960.44 2659.74,1946.26 ; U1.N17@2648.12,1964.88 2659.74,1946.26 ; U16.5@3533.43,1171.86 3499.41,1194 ; U16.5@3533.43,1216.14 3499.41,1194 ; U16.5@3535.97,1176.36 3499.41,1194 ; U16.5@3535.97,1211.64 3499.41,1194 ; U16.5@3537.89,1181.08 3499.41,1194 ; U16.5@3537.89,1206.92 3499.41,1194 ; U16.5@3539.19,1185.95 3499.41,1194 ; U16.5@3539.19,1202.05 3499.41,1194 ; U16.5@3539.88,1190.91 3499.41,1194 ; U16.5@3539.88,1197.09 3499.41,1194 ; U16.5@3540,1194 3490.59,1194 3445.5,1239.09 3445.5,1255.78 3414.28,1287 2967.67,1287 2710,1544.67 2710,1896 2648,1958 U1.N17@2645.38,1962.86 2659.74,1946.26
RXIP0: U1.U15 U14.10 | length 2190.6
  Top w5: U14.10@1098,1190 1129.03,1190 ; U14.10@1098.15,1186.91 1129.03,1190 ; U14.10@1098.15,1193.09 1129.03,1190 ; U14.10@1099.05,1181.98 1129.03,1190 ; U14.10@1099.05,1198.02 1129.03,1190 ; U14.10@1100.76,1177.2 1129.03,1190 ; U14.10@1100.76,1202.8 1129.03,1190 ; U14.10@1103.27,1172.7 1129.03,1190 ; U14.10@1103.27,1207.3 1129.03,1190 ; U14.10@1106.59,1168.57 1129.03,1190 ; U14.10@1106.59,1211.43 1129.03,1190 ; U1.U15@2534.08,1928.71 2522.85,1910.85 ; U1.U15@2539.17,1924.21 2522.85,1910.85 ; 1129.03,1190 1143.46,1204.43 1143.46,1223.35 1371.11,1451 2167,1451 2503,1787 2503,1891 2536.81,1924.81 U1.U15@2536.81,1926.67 2522.85,1910.85
RXIP1: U1.R16 U14.2 | length 1666.8
  Top w5: U14.2@1898,1190 1937,1190 ; U14.2@1898.12,1186.91 1937,1190 ; U14.2@1898.12,1193.09 1937,1190 ; U14.2@1898.84,1181.95 1937,1190 ; U14.2@1898.84,1198.05 1937,1190 ; U14.2@1900.2,1177.1 1937,1190 ; U14.2@1900.2,1202.9 1937,1190 ; U14.2@1902.2,1172.4 1937,1190 ; U14.2@1902.2,1207.6 1937,1190 ; U14.2@1904.84,1167.94 1937,1190 ; U14.2@1904.84,1212.06 1937,1190 ; U1.R16@2587.7,1944.44 2591.1,1926.7 ; U1.R16@2594.49,1944.44 2591.1,1926.7 ; 1937,1190 1942.5,1195.5 1942.5,1245.56 2006.94,1310 2226.5,1310 2626.5,1710 2626.5,1891.3 2591.1,1926.7 ; 2591.1,1926.7 U1.R16@2591.1,1944.76 2591.1,1926.7
RXIP2: U1.P16 U12.10 | length 1488.8
  Top w4.5: U1.P16@2605.55,1962.49 2609.19,1944.81 ; U1.P16@2612.83,1962.49 2609.19,1944.81 ; 2655,1899 2609.19,1944.81 ; 2609.19,1944.81 U1.P16@2609.19,1962.86 2609.19,1944.81
  Top w5: U12.10@2138,1190 2177,1190 ; U12.10@2138.12,1186.91 2177,1190 ; U12.10@2138.12,1193.09 2177,1190 ; U12.10@2138.84,1181.95 2177,1190 ; U12.10@2138.84,1198.05 2177,1190 ; U12.10@2140.2,1177.1 2177,1190 ; U12.10@2140.2,1202.9 2177,1190 ; U12.10@2142.2,1172.4 2177,1190 ; U12.10@2142.2,1207.6 2177,1190 ; U12.10@2144.84,1167.94 2177,1190 ; U12.10@2144.84,1212.06 2177,1190 ; 2655,1899 2657,1897 2657,1667.82 2259,1269.82 2234.82,1269.82 2182.5,1217.5 2182.5,1195.5 2177,1190
RXIP3: U1.M15 U12.1 | length 1471.3
  Top w4.5: v2@2642.2,2017.14 2643.06,2017.14 v2(2643.2,2017)
  Top w8: v2@2642.2,2017.14 U1.M15@2627.29,2017.14 v2(2643.2,2017)
  Bottom w5: v2@2637.85,2015.74 2643.2,2005 ; v2@2648.55,2015.74 2643.2,2005 ; U12.1@3031.16,1167.94 2999,1190 ; U12.1@3031.16,1212.06 2999,1190 ; U12.1@3033.8,1172.4 2999,1190 ; U12.1@3033.8,1207.6 2999,1190 ; U12.1@3035.8,1177.1 2999,1190 ; U12.1@3035.8,1202.9 2999,1190 ; U12.1@3037.16,1181.95 2999,1190 ; U12.1@3037.16,1198.05 2999,1190 ; U12.1@3037.88,1186.91 2999,1190 ; U12.1@3037.88,1193.09 2999,1190 ; U12.1@3038,1190 2999,1190 ; 2643.2,2005 v2(2643.2,2017) 2643.2,2005 ; 2643.2,2005 2710,1938.2 2710,1544.67 2993.5,1261.17 2993.5,1195.5 2999,1190
RXIP4: U1.N16 U16.7 | length 1911.4
  Top w4.5: U1.N16@2623.65,1980.58 2627.29,1962.8 ; U1.N16@2630.92,1980.58 2627.29,1962.8 ; 2647.72,1942.37 2627.29,1962.8 ; 2627.29,1962.8 U1.N16@2627.29,1980.95 2627.29,1962.8
  Top w5: 2647.72,1942.37 2699,1891.09 2699,1540.11 2963.11,1276 3409.72,1276 3434.5,1251.22 3434.5,1239.09 3389.41,1194 U16.7@3340,1194 ; U16.7@3340.12,1190.91 3380.59,1194 ; U16.7@3340.12,1197.09 3380.59,1194 ; U16.7@3340.81,1185.95 3380.59,1194 ; U16.7@3340.81,1202.05 3380.59,1194 ; U16.7@3342.11,1181.08 3380.59,1194 ; U16.7@3342.11,1206.92 3380.59,1194 ; U16.7@3344.03,1176.36 3380.59,1194 ; U16.7@3344.03,1211.64 3380.59,1194 ; U16.7@3346.57,1171.86 3380.59,1194 ; U16.7@3346.57,1216.14 3380.59,1194
S_COMP_1-CPU-RT0: C37.2 R26.1 | length 263.4
  Top w4.5: R26.1@3525.49,2535.09 3535,2513.36 ; C37.2@3527.36,2490.28 3535,2512.5 ; R26.1@3529.79,2536.5 3535,2513.36 ; C37.2@3531.76,2489.22 3535,2512.5 ; C37.2@3535,2489 3535,2536 3533,2538 R26.1@3533,2537 3535,2513.36 ; R26.1@3536.25,2537.05 3535,2513.36 ; C37.2@3538.24,2489.22 3535,2512.5 ; R26.1@3540.73,2536.38 3535,2513.36 ; C37.2@3542.64,2490.28 3535,2512.5
SD_CD_1-CPU-RT0: J44.CD R388.2 U1.P9 | length 5415.9
  Top w4.5: v1@943.78,2527.05 J44.CD@970.35,2534.92 ; v1@944.41,2527.31 J44.CD@970.98,2532.61 ; v1@945.04,2527.5 J44.CD@971.83,2530.51 ; v1@945.41,2522.84 J44.CD@970.35,2534.92 ; v1@945.66,2522.96 J44.CD@970.98,2532.61 ; v1@945.68,2527.64 J44.CD@972.84,2528.4 ; v1@945.92,2523.06 J44.CD@971.83,2530.51 ; v1@946.09,2512.3 J44.CD@975.34,2512.75 ; v1@946.18,2523.15 J44.CD@972.84,2528.4 ; v1@946.37,2516.81 J44.CD@975.34,2512.75 ; v1@946.74,2516.76 J44.CD@975.62,2516.07 ; v1@946.96,2523.25 J44.CD@975.09,2522 ; v1@946.98,2512.25 J44.CD@975.62,2516.07 ; v1@947.09,2516.75 J44.CD@975.52,2519.15 ; v1@947.28,2523.24 J44.CD@975.52,2519.15 ; v1@947.42,2516.78 J44.CD@975.09,2522 ; v1@947.52,2527.73 J44.CD@975.09,2522 ; v1@947.62,2523.19 J44.CD@975.62,2516.07 ; v1@947.82,2512.29 J44.CD@975.52,2519.15 ; v1@947.82,2516.85 J44.CD@974.12,2525.39 ; v1@947.83,2516.86 J44.CD@973.73,2525.39 ; v1@947.98,2523.1 J44.CD@975.34,2512.75 ; v1@948.19,2516.97 J44.CD@972.84,2528.4 ; v1@948.28,2527.64 J44.CD@975.52,2519.15 ; v1@948.44,2517.09 J44.CD@971.83,2530.51 ; v1@948.61,2512.42 J44.CD@975.09,2522 ; v1@948.68,2517.22 J44.CD@970.98,2532.61 ; v1@948.91,2517.37 J44.CD@970.35,2534.92 ; v1@949.08,2527.47 J44.CD@975.62,2516.07 ; v1@949.56,2512.69 J44.CD@974.12,2525.39 ; v1@949.6,2512.7 J44.CD@973.73,2525.39 ; v1@949.9,2527.19 J44.CD@975.34,2512.75 ; v1@950.42,2513.05 J44.CD@972.84,2528.4 ; v1@951.01,2513.37 J44.CD@971.83,2530.51 ; v1@951.55,2513.73 J44.CD@970.98,2532.61 ; v1@952.05,2514.12 J44.CD@970.35,2534.92 ; J44.CD@984.93,2506.74 v1@955.13,2525.39 ; J44.CD@984.93,2544.04 v1@955.13,2525.39 ; J44.CD@987.12,2510.83 v1@955.13,2525.39 ; J44.CD@987.12,2539.96 v1@955.13,2525.39 ; J44.CD@988.74,2515.1 v1@955.13,2525.39 ; J44.CD@988.74,2535.68 v1@955.13,2525.39 ; J44.CD@989.79,2519.51 v1@955.13,2525.39 ; J44.CD@989.79,2531.28 v1@955.13,2525.39 ; J44.CD@990.28,2525.39 v1@955.13,2525.39 ; J44.CD@1008,2525.39 952,2525.39 952,2525 v1(947,2520) ; v2@2476.76,2073.23 U1.P9@2478.89,2089.11 ; v2@2477.23,2075.79 U1.P9@2486.15,2089.1 ; v2@2487.78,2075.78 U1.P9@2478.89,2089.11 ; v2@2488.16,2074.52 U1.P9@2482.52,2089.52 ; v2@2488.16,2074.53 U1.P9@2482.52,2089.52 ; v2@2488.24,2073.21 U1.P9@2486.15,2089.1 ; v1(947,2520) J44.CD@973.73,2525.39 ; v1(947,2520) J44.CD@970.35,2534.92 ; v1(947,2520) J44.CD@975.62,2516.07 ; v1(947,2520) J44.CD@970.98,2532.61 ; v1(947,2520) J44.CD@975.52,2519.15 ; v1(947,2520) J44.CD@971.83,2530.51 ; v1(947,2520) J44.CD@975.09,2522 ; v1(947,2520) J44.CD@972.84,2528.4 ; v1(947,2520) J44.CD@974.12,2525.39 ; v1(947,2520) J44.CD@975.34,2512.75 ; J44.CD@973.73,2525.39 946.56,2527.74 J44.CD@974.12,2525.39 ; J44.CD@973.73,2525.39 946.55,2523.22 J44.CD@974.12,2525.39 ; U1.P9@2478.89,2089.11 v2(2482.5,2073.5) ; v2(2482.5,2073.5) U1.P9@2482.52,2089.52 ; v2(2482.5,2073.5) U1.P9@2486.15,2089.1 ; v2(2482.5,2073.5) U1.P9@2482.52,2089.52 ; U1.P9@2482.52,2089.52 2476.84,2074.53 U1.P9@2482.52,2089.52
  Inner Layer 3 w4.5: v1@939.34,2518.82 947,2494.5 ; v1@943.76,2519.79 947,2494.5 ; v1(947,2520) 947,2342 918,2313 918,1700 1043,1575 2106,1575 2340,1809 2340,1861 2445,1966 2445,2001.5 2482.5,2039 v2(2482.5,2073.5) ; v1@950.24,2519.79 947,2494.5 ; v1@954.66,2518.82 947,2494.5 ; v2@2476.79,2072.8 2482.5,2050 v2@2488.21,2072.8
  Bottom w4.5: v1@945.69,2512.36 R388.2@968.69,2512.36 ; v1@945.69,2527.64 R388.2@968.69,2527.64 ; v1@946.14,2516.87 R388.2@968.69,2512.36 ; v1@946.14,2523.13 R388.2@968.69,2527.64 ; v1@946.77,2516.76 R388.2@969.77,2516.76 ; v1@946.77,2523.24 R388.2@969.77,2523.24 ; v1@947.22,2512.25 R388.2@969.77,2516.76 ; v1@947.22,2527.75 R388.2@969.77,2523.24 ; v1@947.23,2516.76 R388.2@970,2520 ; v1@947.23,2523.24 R388.2@970,2520 ; v1@947.68,2516.82 R388.2@969.77,2523.24 ; v1@947.68,2523.18 R388.2@969.77,2516.76 ; v1@948.31,2512.36 R388.2@970,2520 ; v1@948.29,2517.02 R388.2@968.69,2527.64 ; v1@948.29,2522.98 R388.2@968.69,2512.36 ; v1@948.31,2527.64 R388.2@970,2520 ; v1@949.37,2512.62 R388.2@969.77,2523.24 ; v1@949.37,2527.38 R388.2@969.77,2516.76 ; v1@950.77,2513.23 R388.2@968.69,2527.64 ; v1@950.77,2526.77 R388.2@968.69,2512.36 ; v1(947,2520) R388.2@970,2520 ; v1(947,2520) R388.2@968.69,2512.36 ; v1(947,2520) R388.2@968.69,2527.64 ; v1(947,2520) R388.2@969.77,2516.76 ; v1(947,2520) R388.2@969.77,2523.24
SD_CLK_1-CPU-RT0: C275.1 J44.5 U1.R8 | length 2614.5
  Top w4.5: J44.5@1008,2167.13 1005.13,2170 999,2170 C275.1@1090,2170 ; J44.5@1025.72,2167.13 1060.89,2170 ; J44.5@1025.73,2173.03 1060.89,2170 ; J44.5@1026.41,2177.51 1060.89,2170 ; J44.5@1026.69,2161.3 1060.89,2170 ; J44.5@1027.67,2181.9 1060.89,2170 ; J44.5@1028.08,2156.99 1060.89,2170 ; J44.5@1029.51,2186.15 1060.89,2170 ; J44.5@1030.04,2152.86 1060.89,2170 ; J44.5@1032.55,2148.97 1060.89,2170 ; C275.1@1077.56,2167.82 1088,2146.02 ; C275.1@1081.81,2169.38 1088,2146.02 ; C275.1@1083.72,2162.36 1061.5,2170 ; C275.1@1083.72,2177.64 1061.5,2170 ; C275.1@1084.78,2166.76 1061.5,2170 ; C275.1@1084.78,2173.24 1061.5,2170 ; C275.1@1088.25,2170.19 1088,2146.02 ; C275.1@1092.74,2169.72 1088,2146.02 ; U1.R8@2442.7,2089.15 2446.33,2071.43 ; U1.R8@2449.97,2089.15 2446.33,2071.43 ; 1061.5,2170 C275.1@1085,2170 ; C275.1@1085,2170 C275.1@1090,2170 ; C275.1@1085,2170 1088,2146.02 ; C275.1@1090,2170 1088,2168 1088,2012 1470,1630 2042,1630 2390,1978 2390,2015.1 2446.33,2071.43 ; 2446.33,2071.43 U1.R8@2446.33,2089.52 2446.33,2071.43
SD_CMD_1-CPU-RT0: J44.2 R377.2 U1.R10 | length 3481.7
  Top w4.5: J44.2@1008,1871.85 1009.85,1870 1013,1870 1028,1855 1083,1855 R377.2@1083,1848 ; J44.2@1022.1,1852.79 1062.46,1855 ; J44.2@1022.11,1857.39 1062.46,1855 ; J44.2@1022.63,1861.91 1062.46,1855 ; J44.2@1023.65,1866.32 1062.46,1855 ; J44.2@1025.72,1871.85 1062.46,1855 ; J44.2@1028.56,1877.02 1062.46,1855 ; J44.2@1031.23,1880.67 1062.46,1855 ; J44.2@1034.32,1884.02 1062.46,1855 ; J44.2@1037.8,1887.03 1062.46,1855 ; R377.2@1079.82,1840.93 1057.98,1855 ; R377.2@1081.93,1844.93 1057.98,1855 ; R377.2@1083.68,1851.18 1057.98,1855 ; R377.2@1083.95,1855.69 1057.98,1855 ; v1@1099.66,1836.88 R377.2@1086.14,1855.09 ; v1@1100.88,1835.93 R377.2@1084.01,1851.09 ; v1@1101.86,1835.41 R377.2@1083,1848 ; v1@1102.91,1835.04 R377.2@1082.44,1844.8 ; v1@1102.93,1849.97 R377.2@1082.43,1840.27 ; v1@1103.01,1839.93 R377.2@1086.14,1855.09 ; v1@1103.56,1839.59 R377.2@1084.01,1851.09 ; v1@1103.63,1834.87 R377.2@1083,1842.5 ; v1@1103.63,1850.13 R377.2@1083,1842.5 ; v1@1103.99,1839.41 R377.2@1083,1848 ; v1@1104.43,1834.77 R377.2@1082.43,1840.27 ; v1@1104.44,1839.3 R377.2@1082.44,1844.8 ; v1@1104.45,1845.7 R377.2@1082.43,1840.27 ; v1@1104.46,1850.23 R377.2@1082.44,1844.8 ; v1@1104.76,1839.26 R377.2@1083,1842.5 ; v1@1104.76,1845.74 R377.2@1083,1842.5 ; v1@1105.09,1839.25 R377.2@1082.43,1840.27 ; v1@1105.1,1845.75 R377.2@1082.44,1844.8 ; v1@1105.56,1845.7 R377.2@1083,1848 ; v1@1105.57,1850.23 R377.2@1083,1848 ; v1@1106.01,1845.59 R377.2@1084.01,1851.09 ; v1@1106.61,1845.33 R377.2@1086.14,1855.09 ; v1@1106.67,1850.07 R377.2@1084.01,1851.09 ; v1@1108.14,1849.59 R377.2@1086.14,1855.09 ; 1057.98,1855 R377.2@1083,1848 ; R377.2@1082.43,1840.27 v1(1105,1842.5) ; R377.2@1082.43,1840.27 v1(1105,1842.5) ; R377.2@1082.44,1844.8 v1(1105,1842.5) ; R377.2@1082.44,1844.8 v1(1105,1842.5) ; R377.2@1083,1842.5 R377.2@1083,1848 ; R377.2@1083,1842.5 v1(1105,1842.5) ; R377.2@1083,1842.5 v1(1105,1842.5) ; R377.2@1083,1848 v1(1105,1842.5) ; R377.2@1083,1848 v1(1105,1842.5) ; R377.2@1084.01,1851.09 v1(1105,1842.5) ; R377.2@1084.01,1851.09 v1(1105,1842.5) ; R377.2@1086.14,1855.09 v1(1105,1842.5) ; R377.2@1086.14,1855.09 v1(1105,1842.5)
  Top w8: U1.R10@2482.52,2053.33 2466.07,2053.33 U1.R10@2482.52,2053.33 ; U1.R10@2482.52,2053.33 v2(2466,2053.4) U1.R10@2482.52,2053.33
  Top w11: v2(2466,2053.4) v2@2466.07,2053.33
  Inner Layer 3 w4.5: v1@1097.34,1841.32 1105,1817 ; v1@1101.76,1842.29 1105,1817 ; v1@1108.24,1842.29 1105,1817 ; v1@1112.66,1841.32 1105,1817 ; v2@2460.38,2052.17 2466,2040 ; v2(2466,2053.4) 2466,2040 ; v2@2471.62,2052.17 2466,2040 ; 1105,1817 v1(1105,1842.5) 1105,1607 1127,1585 2102,1585 2330,1813 2330,1870 2430,1970 2430,2004 2466,2040
SD_D0_1-CPU-RT0: J44.7 R376.2 U1.T11 | length 3487.3
  Top w4.5: J44.7@971.68,2365.56 971,2329.18 ; J44.7@976.29,2365.18 971,2329.18 ; J44.7@980.76,2364.23 971,2329.18 ; J44.7@985.04,2362.75 971,2329.18 ; J44.7@990.28,2360.04 971,2329.18 ; J44.7@995.02,2356.51 971,2329.18 ; J44.7@998.23,2353.32 971,2329.18 ; J44.7@1001.04,2349.72 971,2329.18 ; J44.7@1003.4,2345.74 971,2329.18 ; J44.7@1025.72,2360.04 1060.87,2360.04 ; J44.7@1026.21,2354.16 1060.87,2360.04 ; J44.7@1026.21,2365.92 1060.87,2360.04 ; J44.7@1027.26,2349.75 1060.87,2360.04 ; J44.7@1027.26,2370.33 1060.87,2360.04 ; J44.7@1028.88,2345.47 1060.87,2360.04 ; J44.7@1028.88,2374.6 1060.87,2360.04 ; J44.7@1031.07,2341.39 1060.87,2360.04 ; J44.7@1031.07,2378.69 1060.87,2360.04 ; R376.2@1081.8,2349.57 1060.06,2360.04 ; R376.2@1083.37,2353.81 1060.06,2360.04 ; R376.2@1083.73,2364.75 1060.06,2360.04 ; R376.2@1084,2357 1060.06,2360.04 ; R376.2@1084.19,2360.24 1060.06,2360.04 ; R376.2@1085,2357 1081.96,2360.04 1000.83,2360.04 J44.7@1008,2360.04 971,2360.04 971,2329.18 ; U1.T11@2482.15,2013.51 2464.44,2017.14 ; U1.T11@2482.15,2020.78 2464.44,2017.14 ; U1.T11@2482.52,2017.14 2464.44,2017.14 ; 971,2329.18 920,2278.18 920,1663 1013,1570 2107,1570 2350,1813 2350,1866 2443,1959 2443,1995.7 2464.44,2017.14
SD_D1_1-CPU-RT0: J44.8 R375.2 U1.U11 | length 3563.2
  Top w4.5: J44.8@973.66,2436.97 962.33,2399.33 ; J44.8@977.99,2435.39 962.33,2399.33 ; J44.8@982.05,2433.33 962.33,2399.33 ; J44.8@985.83,2430.84 962.33,2399.33 ; J44.8@990.28,2426.97 962.33,2399.33 ; J44.8@994.11,2422.47 962.33,2399.33 ; J44.8@996.56,2418.67 962.33,2399.33 ; J44.8@998.56,2414.58 962.33,2399.33 ; J44.8@1000.1,2410.23 962.33,2399.33 ; J44.8@1025.21,2421.09 1060.96,2421 ; J44.8@1025.49,2416.57 1060.96,2421 ; J44.8@1025.72,2426.97 1060.96,2421 ; J44.8@1026.35,2412.08 1060.96,2421 ; J44.8@1027.18,2432.69 1060.96,2421 ; J44.8@1027.79,2407.68 1060.96,2421 ; J44.8@1028.93,2436.86 1060.96,2421 ; J44.8@1031.21,2440.82 1060.96,2421 ; J44.8@1034.03,2444.5 1060.96,2421 ; R375.2@1081.4,2429.58 1059.44,2421 ; R375.2@1082.05,2414.31 1059.44,2421 ; R375.2@1082.64,2425.23 1059.44,2421 ; R375.2@1082.91,2418.75 1059.44,2421 ; U1.U11@2462.1,2001.87 2454.21,1993 ; U1.U11@2465.78,1995.65 2454.21,1993 ; 1059.44,2421 R375.2@1083,2422 1084,2422 1079.03,2421 1008,2421 J44.8@1008,2426.97 989.97,2426.97 951,2388 951,2325.67 910,2284.67 910,1655 1005,1560 2110.43,1560 2360,1809.57 2360,1861 2454.21,1955.21 2454.21,1993 ; 2454.21,1993 2460.21,1999 U1.U11@2464.43,1999.05 U1.U11@2464.43,1999.05 2454.21,1993
SD_D2_1-CPU-RT0: J44.9 R371.2 U1.T10 | length 2491.9
  Top w4: J44.9@1001.5,1681.5 1015,1668 1015,1664 J44.9@1008,1675
  Top w4.5: J44.9@1024.06,1664.73 1061.31,1664 ; J44.9@1024.25,1660.17 1061.31,1664 ; J44.9@1024.43,1669.24 1061.31,1664 ; J44.9@1025.01,1655.61 1061.31,1664 ; J44.9@1025.72,1675 1061.31,1664 ; J44.9@1027.9,1680.49 1061.31,1664 ; J44.9@1030.15,1684.41 1061.31,1664 ; J44.9@1032.88,1688.07 1061.31,1664 ; J44.9@1036.08,1691.41 1061.31,1664 ; R371.2@1080.5,1656.69 1104.99,1644.01 ; R371.2@1082.9,1660.52 1104.99,1644.01 ; R371.2@1083.4,1655.42 1061.46,1664 ; R371.2@1084.05,1670.69 1061.46,1664 ; R371.2@1084.64,1659.77 1061.46,1664 ; R371.2@1084.91,1666.25 1061.46,1664 ; R371.2@1087.37,1665.22 1104.99,1644.01 ; R371.2@1091.07,1667.81 1104.99,1644.01 ; U1.T10@2464.06,2031.6 2446.34,2035.24 ; U1.T10@2464.06,2038.87 2446.34,2035.24 ; J44.9@1015,1664 R371.2@1085,1664 ; J44.9@1015,1664 J44.9@1008,1675 1001.5,1681.5 994,1689 989,1689 989,1664 J44.9@1015,1664 ; 1061.46,1664 R371.2@1085,1663 ; R371.2@1085,1663 R371.2@1085,1664 ; R371.2@1085,1663 1104.99,1644.01 ; R371.2@1085,1664 1159,1590 2097,1590 2330,1823 2330,1876 2422,1968 2422,2010.9 2446.34,2035.24 ; 2446.34,2035.24 U1.T10@2464.43,2035.24 2446.34,2035.24
SD_D3_1-CPU-RT0: J44.1 R373.2 U1.U10 | length 2906.4
  Top w4.5: J44.1@974.31,1784.44 960.87,1747.87 ; J44.1@978.54,1782.6 960.87,1747.87 ; J44.1@982.47,1780.3 960.87,1747.87 ; J44.1@986.08,1777.58 960.87,1747.87 ; J44.1@990.28,1773.43 960.87,1747.87 ; J44.1@993.81,1768.69 960.87,1747.87 ; J44.1@996,1764.73 960.87,1747.87 ; J44.1@997.73,1760.51 960.87,1747.87 ; J44.1@998.96,1756.07 960.87,1747.87 ; J44.1@1022.94,1758.78 1061.74,1759 ; J44.1@1023.18,1763.34 1061.74,1759 ; J44.1@1023.24,1754.18 1061.74,1759 ; J44.1@1023.94,1767.79 1061.74,1759 ; J44.1@1025.72,1773.43 1061.74,1759 ; J44.1@1028.32,1778.72 1061.74,1759 ; J44.1@1030.84,1782.48 1061.74,1759 ; J44.1@1033.81,1785.94 1061.74,1759 ; J44.1@1037.2,1789.06 1061.74,1759 ; R373.2@1081.55,1747.65 1059.74,1759 ; R373.2@1083.26,1751.83 1059.74,1759 ; R373.2@1084.04,1762.75 1059.74,1759 ; R373.2@1084.32,1758.23 1059.74,1759 ; U1.U10@2443.53,2019.48 2433,2004 ; U1.U10@2448.63,2014.3 2433,2004 ; 1059.74,1759 R373.2@1084,1755 1085,1755 1081,1759 1022.43,1759 J44.1@1008,1773.43 1001.43,1780 993,1780 930,1717 930,1673 1023,1580 2103,1580 2340,1817 2340,1870 2433,1963 2433,2004 ; 2433,2004 2446.14,2017.14 U1.U10@2446.33,2017.14 2433,2004
SD_WP_1-CPU-RT0: J44.WP R389.2 U1.P10 | length 5059.3
  Top w4.5: J44.WP@56.93,2569.47 82.8,2603.85 ; J44.WP@60.84,2566.86 82.8,2603.85 ; J44.WP@64.94,2564.71 82.8,2603.85 ; J44.WP@68.87,2537.37 121.88,2521.75 ; J44.WP@69.2,2563.03 82.8,2603.85 ; J44.WP@70.36,2541.75 121.88,2521.75 ; J44.WP@72.19,2545.94 121.88,2521.75 ; R389.2@72.55,2652.87 82.8,2631.13 ; J44.WP@73.58,2561.83 82.8,2603.85 ; J44.WP@74.35,2549.95 121.88,2521.75 ; J44.WP@76.82,2553.74 121.88,2521.75 ; R389.2@76.8,2654.4 82.8,2631.13 ; R389.2@83.25,2655.16 82.8,2631.13 ; R389.2@87.74,2654.65 82.8,2631.13 ; J44.WP@89.89,2566.81 121.88,2521.75 ; J44.WP@92.03,2561.83 82.8,2603.85 ; J44.WP@93.68,2569.28 121.88,2521.75 ; J44.WP@96.4,2563.03 82.8,2603.85 ; J44.WP@97.69,2571.44 121.88,2521.75 ; J44.WP@100.66,2564.71 82.8,2603.85 ; J44.WP@101.88,2573.27 121.88,2521.75 ; J44.WP@104.77,2566.86 82.8,2603.85 ; J44.WP@106.26,2574.76 121.88,2521.75 ; J44.WP@108.67,2569.47 82.8,2603.85 ; v1@898.82,2327.34 874.5,2335 ; v1@898.82,2342.66 874.5,2335 ; v1@899.79,2331.76 874.5,2335 ; v1@899.79,2338.24 874.5,2335 ; 82.8,2631.13 R389.2@80,2655 81,2655 82.8,2653.2 J44.WP@82.8,2560.83 307.63,2336 307.63,2335 v1(900,2335) 874.5,2335
  Top w8: v2(2500.6,2053.2) U1.P10@2500.62,2071.43 ; v2(2500.6,2053.2) U1.P10@2500.62,2071.43 ; v2(2500.6,2053.2) U1.P10@2500.62,2071.43 ; v2(2500.6,2053.2) U1.P10@2500.62,2071.43
  Inner Layer 3 w4.5: v1@892.81,2332.11 908,2304.69 ; v1@896.9,2334.01 908,2304.69 ; v1@903.18,2335.67 908,2304.69 ; v1@907.68,2336.04 908,2304.69 ; v2@2494.99,2051.95 2500.6,2039.96 ; v2@2506.21,2051.95 2500.6,2039.96 ; 908,2304.69 v1(900,2335) 908,2327 908,1690 1033,1565 2110,1565 2350,1805 2350,1855.01 2460,1964.93 2460,1999.16 2500.6,2039.96 ; 2500.6,2039.96 v2(2500.6,2053.2) 2500.6,2039.96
